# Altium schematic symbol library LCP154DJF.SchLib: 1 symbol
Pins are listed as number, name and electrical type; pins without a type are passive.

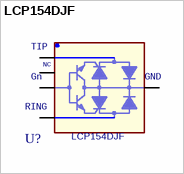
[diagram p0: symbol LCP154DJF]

## LCP154DJF
designator U?
footprint ST_POWERFLAT-5L (Footprint not found)
pins: 1 TIP, 2 NC, 3 Gn, 4 RING, 5 GND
